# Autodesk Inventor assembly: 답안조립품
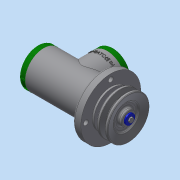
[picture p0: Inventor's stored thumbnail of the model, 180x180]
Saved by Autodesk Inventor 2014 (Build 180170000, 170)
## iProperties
Created: 2016-08
Part Number: 답안조립품
Document SubType Name: Assembly
Designer: 406-9
Author: 406-9
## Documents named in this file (24)
- C:\Users\406-9\Desktop\460807V1019\답안조립품.iam
- C:\Users\406-9\Desktop\460807V1019\본체.ipt
- C:\Users\406-9\Desktop\460807V1019\사이드 커버.ipt
- 사이드 커버.ipt
- C:\Users\406-9\Desktop\460807V1019\탑 커버.ipt
- 탑 커버.ipt
- C:\Users\406-9\Desktop\460807V1019\탑 부시.ipt
- C:\Users\406-9\Desktop\460807V1019\볼트 M4 x 12.ipt
- C:\Users\406-9\Desktop\460807V1019\편심축.ipt
- C:\Users\406-9\Desktop\460807V1019\와셔 10x21.ipt
- C:\Users\406-9\Desktop\460807V1019\부시1.ipt
- C:\Users\406-9\Desktop\460807V1019\너트 M10.ipt
- C:\Users\406-9\Desktop\460807V1019\오일 실 15 25 7.ipt
- C:\Users\406-9\Desktop\460807V1019\베어링 15 x 35 x 11.ipt
- C:\Users\406-9\Desktop\460807V1019\멈춤링 35x1.6.ipt
- C:\Users\406-9\Desktop\460807V1019\키 4 x 4 x 18.ipt
- C:\Users\406-9\Desktop\460807V1019\V-벨트풀리.ipt
- C:\Users\406-9\Desktop\460807V1019\볼트 M4 x 10.ipt
- C:\Users\406-9\Desktop\460807V1019\와셔 4x16.ipt
- C:\Users\406-9\Desktop\460807V1019\슬라이더.ipt
- C:\Users\406-9\Desktop\460807V1019\링크.ipt
- C:\Users\406-9\Desktop\460807V1019\클래스터 핀 6 x 24.ipt
- C:\Users\406-9\Desktop\460807V1019\부시2.ipt
- C:\Users\406-9\Desktop\460807V1019\멈춤링 15 x 1.ipt
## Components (6 placed, 3 different names)
1. V-벨트풀리:1
2. ISO 4017 M4 x 10:1
3. ISO 4762 M4 x 12:1
4. ISO 4762 M4 x 12:2
5. ISO 4762 M4 x 12:3
6. ISO 4762 M4 x 12:4
